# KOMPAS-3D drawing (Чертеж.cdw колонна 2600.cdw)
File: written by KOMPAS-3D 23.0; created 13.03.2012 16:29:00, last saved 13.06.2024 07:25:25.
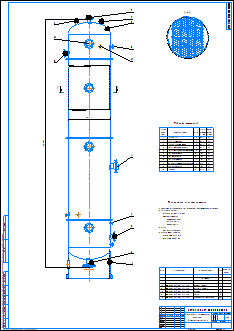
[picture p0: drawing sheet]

Sheet 1: A1, portrait

Document properties: Автор: Comp12; Полное имя файла: G:\Учёба\Чертежи\Колонна К1 АВТ4\Для публикации\Чертеж.cdw колонна 2600.cdw

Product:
- Part/product: (unnamed)  | designation ДУТЭК.18.02.09.ПП.00.00.000

Title block, sheet 1: Наименование: Колонна предварительного / испарения / Чертеж общего вида; Количество листов документа: 1; Форматы листов документа: A1; Литера: У; stored path: G:\Хуснуллин МЗз 07-01\Чертеж.cdw колонна 2600.cdw

Views: Вид 1
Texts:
  Normal
  Поз.
  Кол.
  Приме-
  чание
  Детали
  УТЭК.18.02.09.ПП.00.00.001
  Нижнее днище
  УТЭК.18.02.09.ПП.00.00.002
  Верхнее днище
  УТЭК.18.02.09.ПП.00.00.003
  Корпус
  УТЭК.18.02.09.ПП.00.00.004
  Опора
  УТЭК.18.02.09.ПП.00.00.005
  Колпачковые тарелки
  Техническая характеристика
  1 Аппарат предназначен для получения узкой фракции бензина
  Таблица штуцеров
  Обоз-
  нач-
  ение
  Ввод сырья
  Кол
  Проход
  условный,
  Dy, мм
  Давление
  условное,
  Рy, МПа
  Ввод  орошения
  Ввод горячей струи
  Выход фракции нк-100
  Вывод отбензиненной нефти
  Для манометра
  Для термопары
  Для воздушника
  Для предохранительного клапана
  Для уровнемера
  Люк-лаз
Dimensions and other numbers on the sheet: 1; 2; 3; 4; 5; 24; 24250; 2600; 2 Рабочие условия:; 3 Среда:; 4 Габаритные размеры:; 300; 1,6; 200; 50; 100; 500; 1:25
